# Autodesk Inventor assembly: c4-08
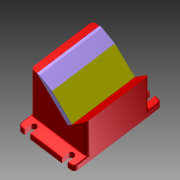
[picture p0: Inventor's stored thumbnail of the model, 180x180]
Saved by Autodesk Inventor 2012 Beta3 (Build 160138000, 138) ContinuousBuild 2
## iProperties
Created: 2010-11
Part Number: c4-08
Document SubType Name: Assembly
Designer: Beta-8540w
Author: Beta-8540w
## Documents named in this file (3)
- C:\Inventor 2012 Essentials\Assemblies\Chapter 4\c4-08.iam
- C:\Inventor 2012 Essentials\Parts\Chapter 4\c4-07.ipt
- C:\Inventor 2012 Essentials\Parts\Chapter 4\c4-08.ipt
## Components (2 placed, 2 different names)
1. c4-07:1 — Mate:1, Mate:2, Flush:1
2. c4-08:1 — Mate:1, Mate:2, Flush:1
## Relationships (3: Mate 2, Flush 1)
- Mate:1: c4-07:1 ↔ c4-08:1
- Mate:2: c4-07:1 ↔ c4-08:1
- Flush:1: c4-07:1 ↔ c4-08:1
